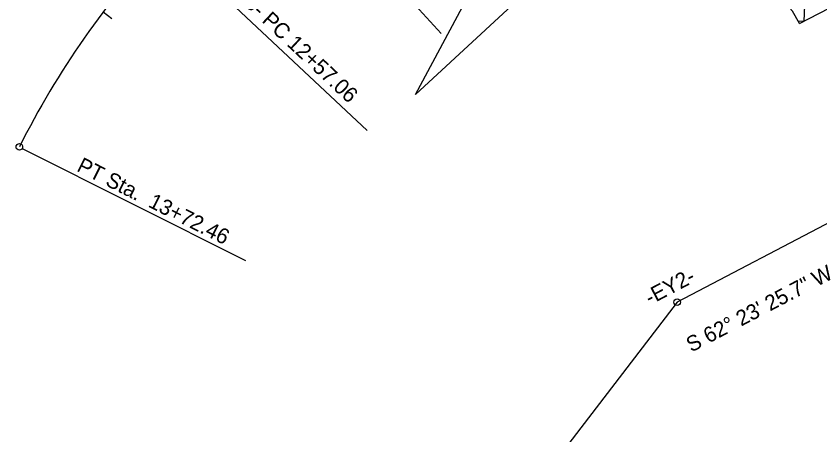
# Model space of a CAD drawing. Extents: x 1702862 to 1704514, y 793768 to 796215.
# Drawn here: x 1703090.2 to 1703456.2, y 794813.2 to 795003.7 of the extents above; entities that cross this region are included whole.
import ezdxf

# ---------------------------------------------------------------- set-up
doc = ezdxf.new("R2010")
doc.units = 0
for name, color, linetype in [('Exist Horizontal Alignment', 7, 'Continuous'), ('Exist Horizontal Alignment Direction Label', 7, 'Continuous'), ('Exist Horizontal Alignment Station Label', 7, 'Continuous'), ('Prop Dimension', 7, 'Continuous'), ('Prop Horizontal Alignment', 7, 'Continuous'), ('Prop Horizontal Alignment Station Label', 7, 'Continuous'), ('Prop Horizontal Alignment Tick Small', 7, 'Continuous'), ('Prop Leader Line Medium', 7, 'Continuous'), ('Prop Rem of Exist Asph Pvmt', 7, 'Continuous')]:
    doc.layers.add(name, color=color, linetype=linetype)

msp = doc.modelspace()

# ---------------------------------------------------------------- linework, layer by layer
at = {"layer": 'Exist Horizontal Alignment'}
msp.add_line((1703731.56, 795051.6), (1703391.21, 794873.6), dxfattribs=at)
at = {"layer": 'Exist Horizontal Alignment Station Label'}
msp.add_lwpolyline([(1703391.21, 794873.6), (1703322.49, 794783.98), (1703405.46, 794694.11)], dxfattribs=at)
msp.add_circle((1703391.21, 794873.6), 1.5, dxfattribs=at)
at = {"layer": 'Prop Dimension'}
for q in [(1703366.77, 795144.26), (1703418.98, 795103.79)]:
    msp.add_line((1703272.02, 794968.13), q, dxfattribs=at)
msp.add_arc((1703324.13, 795065.01), 90, 136.7565, 136.7565, dxfattribs=at)
at = {"layer": 'Prop Horizontal Alignment'}
msp.add_arc((1703449.23, 794764.8), 400, 136.823, 153.353, dxfattribs=at)
at = {"layer": 'Prop Horizontal Alignment Station Label'}
for p, q in [((1703158.62, 795037.47), (1703250, 794951.74)), ((1703093.05, 794943.52), (1703194.68, 794892.53))]:
    msp.add_line(p, q, dxfattribs=at)
msp.add_circle((1703091.71, 794944.2), 1.5, dxfattribs=at)
at = {"layer": 'Prop Horizontal Alignment Tick Small'}
msp.add_line((1703129.88, 795005.67), (1703133.88, 795002.66), dxfattribs=at)
at = {"layer": 'Prop Leader Line Medium'}
msp.add_line((1703214.05, 795071.43), (1703283.79, 794995.89), dxfattribs=at)
at = {"layer": 'Prop Rem of Exist Asph Pvmt'}
for p, q in [((1703450.06, 795032.37), (1703448.82, 795001.4)), ((1703446.88, 795000.39), (1703470.79, 795012.78)), ((1703446.88, 795000.39), (1703470.79, 795012.78)), ((1703446.18, 795001.59), (1703448.97, 795001.48))]:
    msp.add_line(p, q, dxfattribs=at)
msp.add_lwpolyline([(1703446.88, 795000.39), (1703443.63, 795005.93), (1703413.93, 795039.78), (1703381.07, 795076.19), (1703353.81, 795105.47)], dxfattribs=at)

# ---------------------------------------------------------------- texts
at = {"layer": 'Exist Horizontal Alignment Direction Label'}
for s, p in [('S 62%%d 23\' 25.7" W', (1703397.64, 794850.61)), ('-EY2-', (1703378.79, 794872.12))]:
    msp.add_text(s, height=7, rotation=27.6095, dxfattribs=at).set_placement(p)
at = {"layer": 'Prop Horizontal Alignment Station Label'}
for s, rotation, p in [('-LOOPB- PC 12+57.06', 316.823, (1703171.76, 795029.45)), ('PT Sta.  13+72.46', 333.353, (1703117.4, 794933.5))]:
    msp.add_text(s, height=7, rotation=rotation, dxfattribs=at).set_placement(p)

doc.saveas('drawing.dxf')
